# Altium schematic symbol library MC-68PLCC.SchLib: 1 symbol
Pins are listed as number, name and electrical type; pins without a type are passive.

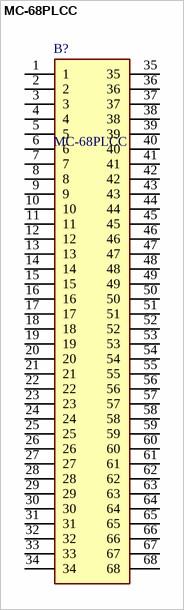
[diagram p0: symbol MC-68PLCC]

## MC-68PLCC
designator B?
SOCKET, PLCC, 68 PIN, THRU-HOLE; Manufacturer_Name: MULTICOMP; Geometry.Height: 8.1mm
footprint MC68PLCC
pins: 1, 2, 3, 4, 5, 6, 7, 8, 9, 10, 11, 12, 13, 14, 15, 16, 17, 18, 19, 20, 21, 22, 23, 24, 25, 26, 27, 28, 29, 30, 31, 32, 33, 34, 35, 36, 37, 38, 39, 40, 41, 42, 43, 44, 45, 46, 47, 48, 49, 50, 51, 52, 53, 54, 55, 56, 57, 58, 59, 60, 61, 62, 63, 64, 65, 66, 67, 68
